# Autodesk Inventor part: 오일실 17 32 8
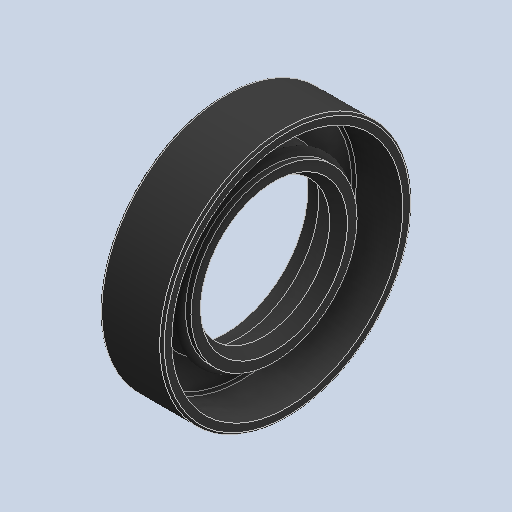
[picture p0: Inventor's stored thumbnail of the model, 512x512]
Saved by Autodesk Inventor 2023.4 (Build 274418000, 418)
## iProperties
Created: 2024-09
Part Number: 오일실 17 32 8
Material: 고무
Description: 오일-실
Document SubType Name: Modeling
Designer: EDU
Density: 0.93 g/cm^3
Appearance: 기본값
Author: jhkim
Sending System: Autodesk Inventor 2025
Preprocessor: ST-DEVELOPER v20
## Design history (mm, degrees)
feature "Solid1"
node "솔리드1"
